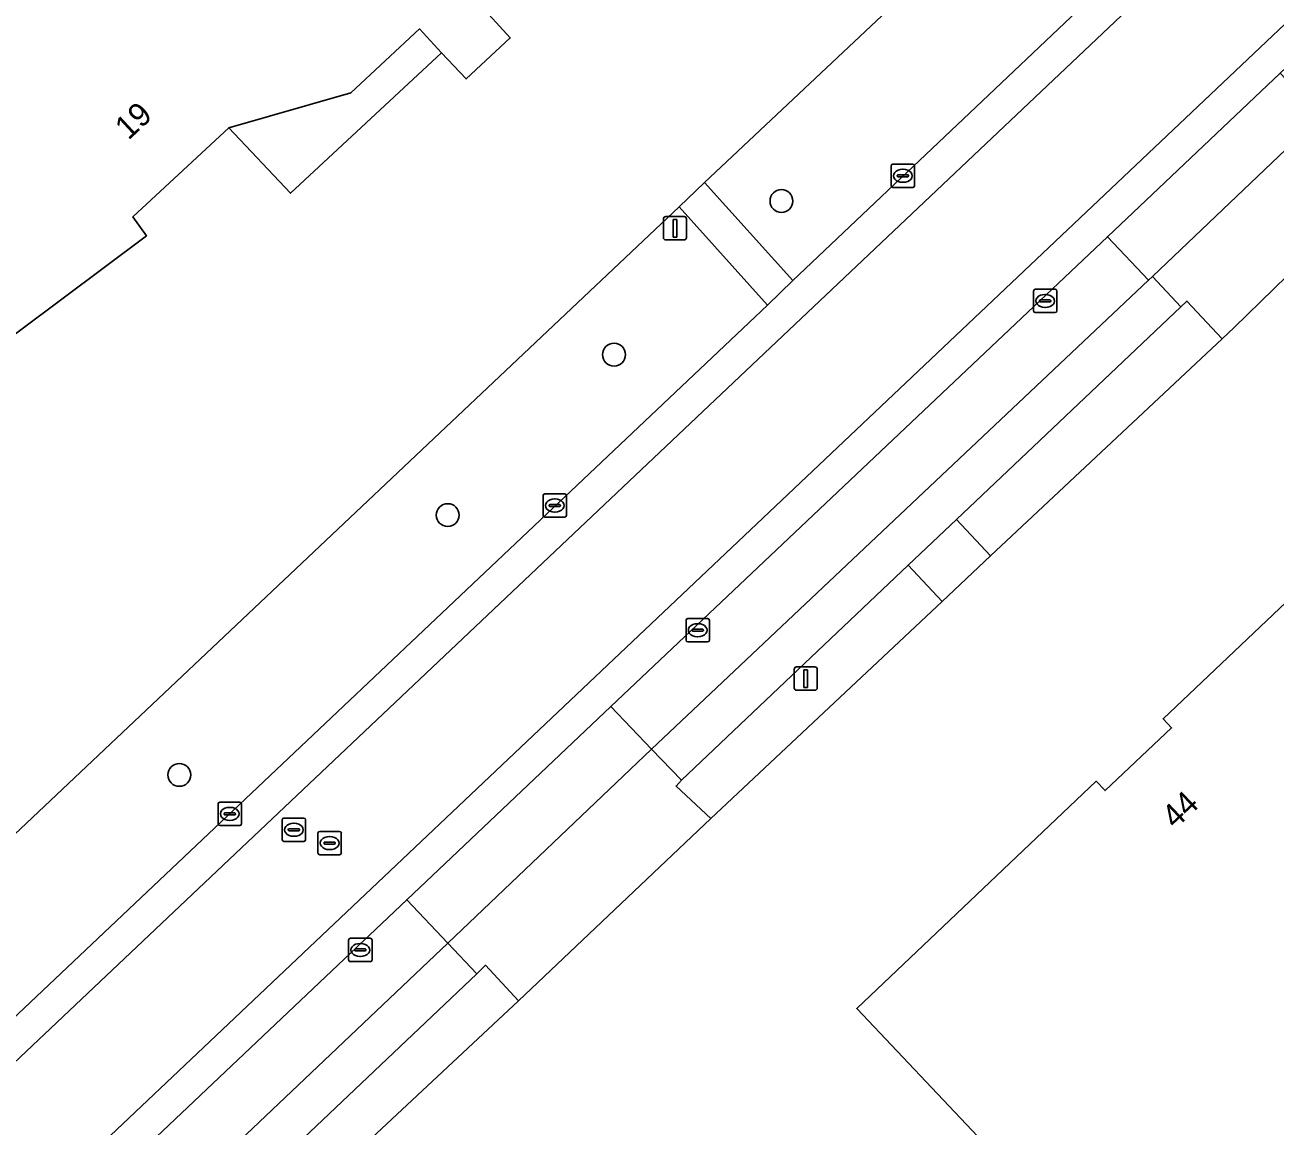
# Model space of a CAD drawing. Extents: x 156702 to 158052, y 387630 to 388992.
# Drawn here: x 157741 to 157794.6, y 388411.3 to 388458.5 of the extents above; entities that cross this region are included whole.
import ezdxf

# ---------------------------------------------------------------- set-up
doc = ezdxf.new("R2010")
doc.units = 0
for name, color, linetype in [('IMGEO_Berm_groen', 7, 'Continuous'), ('IMGEO_Boom', 7, 'Continuous'), ('IMGEO_Erf', 7, 'Continuous'), ('IMGEO_Groenvoorziening', 7, 'Continuous'), ('IMGEO_Kolk', 7, 'Continuous'), ('IMGEO_Lichtmast', 7, 'Continuous'), ('IMGEO_Pand', 7, 'Continuous'), ('IMGEO_Pand_nummerreeks', 7, 'Continuous'), ('IMGEO_Pand_overbouw', 7, 'Continuous'), ('IMGEO_Parkeervlak_open', 7, 'Continuous'), ('IMGEO_Rijbaan_lokaal_gesloten', 7, 'Continuous'), ('IMGEO_Rioolput', 7, 'Continuous'), ('IMGEO_Verkeersbordpaal', 7, 'Continuous'), ('IMGEO_Voetpad_open', 7, 'Continuous')]:
    doc.layers.add(name, color=color, linetype=linetype)

msp = doc.modelspace()

# ---------------------------------------------------------------- linework, layer by layer
at = {"layer": 'IMGEO_Berm_groen'}
msp.add_lwpolyline([(157799.053, 388483.441), (157798.811, 388483.771), (157794.961, 388480.951), (157795.152, 388480.693), (157796.754, 388477.777), (157795.516, 388475.573), (157788.977, 388469.333), (157788.87, 388469.419), (157770.108, 388451.766), (157773.891, 388447.573), (157795.288, 388467.846)], dxfattribs=at)
msp.add_lwpolyline([(157772.807, 388446.508), (157769.024, 388450.72), (157715.141, 388399.858), (157717.133, 388397.781), (157719.197, 388399.804), (157721.207, 388397.728)], close=True, dxfattribs=at)
at = {"layer": 'IMGEO_Boom'}
for centre in [(157773.406, 388450.975), (157766.234, 388444.394), (157759.109, 388437.518), (157747.611, 388426.388)]:
    msp.add_circle(centre, 0.489, dxfattribs=at)
at = {"layer": 'IMGEO_Erf'}
for points in [[(157780.944, 388485.335), (157784.71, 388481.246), (157762.612, 388460.811), (157761.599, 388461.832), (157759.801, 388460.159), (157761.786, 388457.966), (157759.898, 388456.205), (157758.849, 388457.329), (157757.899, 388458.347), (157754.963, 388455.611), (157749.735, 388454.115), (157745.623, 388450.301), (157746.202, 388449.487), (157707.991, 388420.9), (157704.997, 388424.904), (157689.835, 388445.184), (157694.111, 388448.366), (157686.05, 388459.123), (157681.815, 388464.773), (157694.419, 388474.218), (157682.965, 388489.503), (157670.362, 388480.058), (157658.428, 388495.983)], [(157828.567, 388476.717), (157827.02, 388475.574), (157819.744, 388469.314), (157819.109, 388469.983), (157810.78, 388462.732), (157797.894, 388450.521), (157792.808, 388445.559), (157792.292, 388445.075), (157782.368, 388435.768), (157780.291, 388433.819), (157770.375, 388424.519), (157762.137, 388416.71), (157750.411, 388405.749), (157741.215, 388396.791), (157739.918, 388395.57), (157734.391, 388390.366), (157712.553, 388369.817), (157711.355, 388368.682), (157705.627, 388363.261), (157681.507, 388340.173), (157681.329, 388340.003), (157675.827, 388334.804), (157653.403, 388313.608)], [(157627.449, 388318.044), (157654.429, 388341.395), (157664.141, 388350.795), (157692.355, 388378.104), (157701.62, 388386.983), (157703.834, 388389.244), (157706.743, 388391.918), (157715.141, 388399.858), (157769.024, 388450.72), (157770.108, 388451.766), (157788.87, 388469.419)]]:
    msp.add_lwpolyline(points, dxfattribs=at)
msp.add_lwpolyline([(157828.903, 388399.086), (157819.659, 388390.335), (157810.015, 388381.225), (157800.203, 388391.612), (157786.92, 388405.336), (157787, 388405.411), (157776.631, 388416.385), (157786.895, 388426.115), (157787.273, 388425.716), (157790.124, 388428.402), (157789.758, 388428.796), (157800.014, 388438.514), (157800.858, 388437.621), (157810.402, 388427.538), (157805.987, 388423.319), (157811.695, 388417.284)], close=True, dxfattribs=at)
at = {"layer": 'IMGEO_Groenvoorziening'}
for points in [[(157792.292, 388445.075), (157790.778, 388446.688), (157790.516, 388446.44), (157780.903, 388437.33), (157782.368, 388435.768)], [(157780.291, 388433.819), (157778.835, 388435.371), (157769.122, 388426.166), (157768.891, 388425.91), (157770.375, 388424.519)], [(157741.215, 388396.791), (157750.411, 388405.749), (157762.137, 388416.71), (157760.733, 388418.234), (157760.352, 388417.858), (157740.012, 388398.572), (157739.731, 388398.3)]]:
    msp.add_lwpolyline(points, close=True, dxfattribs=at)
at = {"layer": 'IMGEO_Kolk'}
for p, q in [((157778.184, 388452.557), (157779.036, 388452.557)), ((157778.109, 388451.631), (157778.109, 388452.483)), ((157778.368, 388452.051), (157778.368, 388452.063)), ((157778.806, 388452.014), (157778.408, 388452.014)), ((157778.411, 388452.1), (157778.809, 388452.1)), ((157778.597, 388452.337), (157778.622, 388452.337)), ((157778.852, 388452.063), (157778.852, 388452.051)), ((157779.11, 388452.483), (157779.11, 388451.631)), ((157779.036, 388451.557), (157778.184, 388451.557)), ((157778.62, 388451.777), (157778.595, 388451.777)), ((157784.282, 388447.193), (157785.134, 388447.193)), ((157784.207, 388446.267), (157784.207, 388447.119)), ((157784.466, 388446.687), (157784.466, 388446.699)), ((157784.904, 388446.65), (157784.506, 388446.65)), ((157784.509, 388446.736), (157784.907, 388446.736)), ((157784.695, 388446.973), (157784.72, 388446.973)), ((157784.95, 388446.699), (157784.95, 388446.687)), ((157785.208, 388447.119), (157785.208, 388446.267)), ((157785.134, 388446.193), (157784.282, 388446.193)), ((157784.718, 388446.413), (157784.693, 388446.413)), ((157763.196, 388437.504), (157763.196, 388438.356)), ((157763.271, 388438.43), (157764.123, 388438.43)), ((157763.684, 388438.21), (157763.709, 388438.21)), ((157764.197, 388438.356), (157764.197, 388437.504)), ((157763.455, 388437.924), (157763.455, 388437.936)), ((157763.893, 388437.887), (157763.495, 388437.887)), ((157763.498, 388437.973), (157763.896, 388437.973)), ((157763.707, 388437.65), (157763.682, 388437.65)), ((157763.939, 388437.936), (157763.939, 388437.924)), ((157764.123, 388437.43), (157763.271, 388437.43)), ((157769.318, 388432.16), (157769.318, 388433.012)), ((157769.393, 388433.086), (157770.245, 388433.086)), ((157769.806, 388432.866), (157769.831, 388432.866)), ((157770.319, 388433.012), (157770.319, 388432.16)), ((157769.577, 388432.58), (157769.577, 388432.592)), ((157770.015, 388432.543), (157769.617, 388432.543)), ((157769.62, 388432.629), (157770.018, 388432.629)), ((157769.829, 388432.306), (157769.804, 388432.306)), ((157770.061, 388432.592), (157770.061, 388432.58)), ((157770.245, 388432.086), (157769.393, 388432.086)), ((157749.344, 388425.217), (157750.196, 388425.217)), ((157749.269, 388424.291), (157749.269, 388425.143)), ((157749.528, 388424.711), (157749.528, 388424.723)), ((157749.966, 388424.674), (157749.568, 388424.674)), ((157749.571, 388424.76), (157749.969, 388424.76)), ((157749.757, 388424.997), (157749.782, 388424.997)), ((157750.012, 388424.723), (157750.012, 388424.711)), ((157750.27, 388425.143), (157750.27, 388424.291)), ((157750.196, 388424.217), (157749.344, 388424.217)), ((157749.78, 388424.437), (157749.755, 388424.437)), ((157754.864, 388418.46), (157754.864, 388419.312)), ((157754.939, 388419.386), (157755.791, 388419.386)), ((157755.865, 388419.312), (157755.865, 388418.46)), ((157755.123, 388418.88), (157755.123, 388418.892)), ((157755.561, 388418.843), (157755.163, 388418.843)), ((157755.166, 388418.929), (157755.564, 388418.929)), ((157755.352, 388419.166), (157755.377, 388419.166)), ((157755.607, 388418.892), (157755.607, 388418.88)), ((157755.791, 388418.386), (157754.939, 388418.386)), ((157755.375, 388418.606), (157755.35, 388418.606))]:
    msp.add_line(p, q, dxfattribs=at)
for points in [[(157778.184, 388452.557), (157779.036, 388452.557)], [(157778.109, 388451.631), (157778.109, 388452.483)], [(157779.11, 388452.483), (157779.11, 388451.631)], [(157779.036, 388451.557), (157778.184, 388451.557)], [(157784.282, 388447.193), (157785.134, 388447.193)], [(157784.207, 388446.267), (157784.207, 388447.119)], [(157785.208, 388447.119), (157785.208, 388446.267)], [(157785.134, 388446.193), (157784.282, 388446.193)], [(157763.196, 388437.504), (157763.196, 388438.356)], [(157763.271, 388438.43), (157764.123, 388438.43)], [(157764.197, 388438.356), (157764.197, 388437.504)], [(157764.123, 388437.43), (157763.271, 388437.43)], [(157769.318, 388432.16), (157769.318, 388433.012)], [(157769.393, 388433.086), (157770.245, 388433.086)], [(157770.319, 388433.012), (157770.319, 388432.16)], [(157770.245, 388432.086), (157769.393, 388432.086)], [(157749.344, 388425.217), (157750.196, 388425.217)], [(157749.269, 388424.291), (157749.269, 388425.143)], [(157750.27, 388425.143), (157750.27, 388424.291)], [(157750.196, 388424.217), (157749.344, 388424.217)], [(157754.864, 388418.46), (157754.864, 388419.312)], [(157754.939, 388419.386), (157755.791, 388419.386)], [(157755.865, 388419.312), (157755.865, 388418.46)], [(157755.791, 388418.386), (157754.939, 388418.386)]]:
    msp.add_lwpolyline(points, dxfattribs=at)
for centre, radius, start, end in [((157778.186, 388452.481), 0.0765, 91.552, 178.448), ((157778.186, 388452.481), 0.0765, 91.552, 178.448), ((157779.034, 388452.481), 0.0765, 1.552, 88.448), ((157779.034, 388452.481), 0.0765, 1.552, 88.448), ((157778.408, 388452.06), 0.0403, 85.8775, 175.7526), ((157778.405, 388452.05), 0.0366, 178.938, 274.7102), ((157778.809, 388452.057), 0.043, 264.8664, 352.4533), ((157778.813, 388452.062), 0.0386, 1.7309, 96.639), ((157778.186, 388451.633), 0.0765, 181.552, 268.448), ((157778.186, 388451.633), 0.0765, 181.552, 268.448), ((157779.034, 388451.633), 0.0765, 271.552, 358.448), ((157779.034, 388451.633), 0.0765, 271.552, 358.448), ((157784.284, 388447.117), 0.0765, 91.552, 178.448), ((157784.284, 388447.117), 0.0765, 91.552, 178.448), ((157785.132, 388447.117), 0.0765, 1.552, 88.448), ((157785.132, 388447.117), 0.0765, 1.552, 88.448), ((157784.506, 388446.696), 0.0403, 85.8775, 175.7526), ((157784.503, 388446.686), 0.0366, 178.938, 274.7102), ((157784.907, 388446.693), 0.043, 264.8664, 352.4533), ((157784.911, 388446.698), 0.0386, 1.7309, 96.639), ((157784.284, 388446.269), 0.0765, 181.552, 268.448), ((157784.284, 388446.269), 0.0765, 181.552, 268.448), ((157785.132, 388446.269), 0.0765, 271.552, 358.448), ((157785.132, 388446.269), 0.0765, 271.552, 358.448), ((157763.273, 388438.354), 0.0765, 91.552, 178.448), ((157763.273, 388438.354), 0.0765, 91.552, 178.448), ((157764.121, 388438.354), 0.0765, 1.552, 88.448), ((157764.121, 388438.354), 0.0765, 1.552, 88.448), ((157763.273, 388437.506), 0.0765, 181.552, 268.448), ((157763.273, 388437.506), 0.0765, 181.552, 268.448), ((157763.495, 388437.933), 0.0403, 85.8775, 175.7526), ((157763.492, 388437.923), 0.0366, 178.938, 274.7102), ((157763.896, 388437.93), 0.043, 264.8664, 352.4533), ((157763.9, 388437.935), 0.0386, 1.7309, 96.639), ((157764.121, 388437.506), 0.0765, 271.552, 358.448), ((157764.121, 388437.506), 0.0765, 271.552, 358.448), ((157769.395, 388433.01), 0.0765, 91.552, 178.448), ((157769.395, 388433.01), 0.0765, 91.552, 178.448), ((157770.243, 388433.01), 0.0765, 1.552, 88.448), ((157770.243, 388433.01), 0.0765, 1.552, 88.448), ((157769.395, 388432.162), 0.0765, 181.552, 268.448), ((157769.395, 388432.162), 0.0765, 181.552, 268.448), ((157769.617, 388432.589), 0.0403, 85.8775, 175.7526), ((157769.614, 388432.579), 0.0366, 178.938, 274.7102), ((157770.018, 388432.586), 0.043, 264.8664, 352.4533), ((157770.022, 388432.591), 0.0386, 1.7309, 96.639), ((157770.243, 388432.162), 0.0765, 271.552, 358.448), ((157770.243, 388432.162), 0.0765, 271.552, 358.448), ((157749.346, 388425.141), 0.0765, 91.552, 178.448), ((157749.346, 388425.141), 0.0765, 91.552, 178.448), ((157750.194, 388425.141), 0.0765, 1.552, 88.448), ((157750.194, 388425.141), 0.0765, 1.552, 88.448), ((157749.568, 388424.72), 0.0403, 85.8775, 175.7526), ((157749.565, 388424.71), 0.0366, 178.938, 274.7102), ((157749.969, 388424.717), 0.043, 264.8664, 352.4533), ((157749.973, 388424.722), 0.0386, 1.7309, 96.639), ((157749.346, 388424.293), 0.0765, 181.552, 268.448), ((157749.346, 388424.293), 0.0765, 181.552, 268.448), ((157750.194, 388424.293), 0.0765, 271.552, 358.448), ((157750.194, 388424.293), 0.0765, 271.552, 358.448), ((157754.941, 388419.31), 0.0765, 91.552, 178.448), ((157754.941, 388419.31), 0.0765, 91.552, 178.448), ((157755.789, 388419.31), 0.0765, 1.552, 88.448), ((157755.789, 388419.31), 0.0765, 1.552, 88.448), ((157755.163, 388418.889), 0.0403, 85.8775, 175.7526), ((157755.16, 388418.879), 0.0366, 178.938, 274.7102), ((157755.564, 388418.886), 0.043, 264.8664, 352.4533), ((157755.568, 388418.891), 0.0386, 1.7309, 96.639), ((157754.941, 388418.462), 0.0765, 181.552, 268.448), ((157754.941, 388418.462), 0.0765, 181.552, 268.448), ((157755.789, 388418.462), 0.0765, 271.552, 358.448), ((157755.789, 388418.462), 0.0765, 271.552, 358.448)]:
    msp.add_arc(centre, radius, start, end, dxfattribs=at)
for centre, major_axis, ratio, start_param, end_param in [((157778.596, 388452.057), (-0.387, 0.002), 0.722429, 4.712389, 7.853982), ((157778.621, 388452.057), (-0.39, 0.002), 0.717154, 1.570796, 4.712389), ((157784.694, 388446.693), (-0.387, 0.002), 0.722429, 4.712389, 7.853982), ((157784.719, 388446.693), (-0.39, 0.002), 0.717154, 1.570796, 4.712389), ((157763.683, 388437.93), (-0.387, 0.002), 0.722429, 4.712389, 7.853982), ((157763.708, 388437.93), (-0.39, 0.002), 0.717154, 1.570796, 4.712389), ((157769.805, 388432.586), (-0.387, 0.002), 0.722429, 4.712389, 7.853982), ((157769.83, 388432.586), (-0.39, 0.002), 0.717154, 1.570796, 4.712389), ((157749.756, 388424.717), (-0.387, 0.002), 0.722429, 4.712389, 7.853982), ((157749.781, 388424.717), (-0.39, 0.002), 0.717154, 1.570796, 4.712389), ((157755.351, 388418.886), (-0.387, 0.002), 0.722429, 4.712389, 7.853982), ((157755.376, 388418.886), (-0.39, 0.002), 0.717154, 1.570796, 4.712389)]:
    msp.add_ellipse(centre, major_axis=major_axis, ratio=ratio, start_param=start_param, end_param=end_param, dxfattribs=at)
at = {"layer": 'IMGEO_Lichtmast'}
for p, q in [((157773.952, 388430.112), (157773.952, 388430.912)), ((157773.952, 388430.912), (157773.952, 388430.112)), ((157774.052, 388431.012), (157774.842, 388431.012)), ((157774.842, 388431.012), (157774.052, 388431.012)), ((157774.942, 388430.912), (157774.942, 388430.112)), ((157774.942, 388430.112), (157774.942, 388430.912)), ((157774.842, 388430.012), (157774.052, 388430.012)), ((157774.052, 388430.012), (157774.842, 388430.012))]:
    msp.add_line(p, q, dxfattribs=at)
msp.add_lwpolyline([(157774.372, 388430.887), (157774.522, 388430.887), (157774.522, 388430.137), (157774.372, 388430.137), (157774.372, 388430.887)], dxfattribs=at)
for centre, start, end in [((157774.052, 388430.912), 90, 180), ((157774.052, 388430.912), 90, 180), ((157774.842, 388430.912), 0, 90), ((157774.842, 388430.912), 360, 90), ((157774.052, 388430.112), 180, 270), ((157774.052, 388430.112), 180, 270), ((157774.842, 388430.112), 270, 0), ((157774.842, 388430.112), 270, 0)]:
    msp.add_arc(centre, 0.1, start, end, dxfattribs=at)
at = {"layer": 'IMGEO_Pand'}
msp.add_lwpolyline([(157658.428, 388495.983), (157670.362, 388480.058), (157682.965, 388489.503), (157694.419, 388474.218), (157681.815, 388464.773), (157686.05, 388459.123), (157694.111, 388448.366), (157689.835, 388445.184), (157704.997, 388424.904), (157707.991, 388420.9), (157746.202, 388449.487), (157745.623, 388450.301), (157749.735, 388454.115), (157754.963, 388455.611), (157757.899, 388458.347), (157758.849, 388457.329), (157759.898, 388456.205), (157761.786, 388457.966), (157759.801, 388460.159), (157761.599, 388461.832), (157762.612, 388460.811), (157784.71, 388481.246), (157780.944, 388485.335)], dxfattribs=at)
msp.add_lwpolyline([(157800.858, 388437.621), (157800.014, 388438.514), (157789.758, 388428.796), (157790.124, 388428.402), (157787.273, 388425.716), (157786.895, 388426.115), (157776.631, 388416.385), (157787, 388405.411), (157786.92, 388405.336), (157800.203, 388391.612), (157810.015, 388381.225), (157819.659, 388390.335), (157828.903, 388399.086), (157811.695, 388417.284), (157805.987, 388423.319), (157810.402, 388427.538)], close=True, dxfattribs=at)
at = {"layer": 'IMGEO_Pand_overbouw'}
msp.add_lwpolyline([(157758.849, 388457.329), (157757.899, 388458.347), (157754.963, 388455.611), (157749.735, 388454.115), (157752.367, 388451.307)], close=True, dxfattribs=at)
at = {"layer": 'IMGEO_Parkeervlak_open'}
for points in [[(157789.133, 388447.581), (157787.371, 388449.448), (157766.1, 388429.315), (157767.832, 388427.485)], [(157759.112, 388419.181), (157757.354, 388421.039), (157736.97, 388401.746), (157738.748, 388399.867)]]:
    msp.add_lwpolyline(points, close=True, dxfattribs=at)
at = {"layer": 'IMGEO_Rijbaan_lokaal_gesloten'}
for points in [[(157925.989, 388541.781), (157925.789, 388544.405), (157924.816, 388544.354), (157921.978, 388543.651), (157920.425, 388542.954), (157916.373, 388540.433), (157884.271, 388521.013), (157881.592, 388519.374), (157838.65, 388493.098), (157832.229, 388488.942), (157827.136, 388485.429), (157822.012, 388481.702), (157814.126, 388475.59), (157808.05, 388470.514), (157801.977, 388465.115), (157800.565, 388463.859), (157728.664, 388395.811), (157729.626, 388394.795), (157736.97, 388401.746), (157757.354, 388421.039), (157766.1, 388429.315), (157787.371, 388449.448), (157794.773, 388456.453), (157801.348, 388462.676)], [(157722.575, 388397.084), (157798.497, 388468.895), (157797.546, 388469.921), (157795.288, 388467.846), (157773.891, 388447.573), (157772.807, 388446.508), (157721.207, 388397.728), (157693.937, 388371.932), (157669.377, 388348.694), (157655.751, 388335.812), (157635.35, 388316.566)], [(157640.155, 388312.044), (157727.538, 388394.745), (157728.664, 388395.811), (157800.565, 388463.859), (157801.977, 388465.115), (157798.497, 388468.895), (157722.575, 388397.084), (157652.853, 388331.137), (157631.518, 388311.458)]]:
    msp.add_lwpolyline(points, dxfattribs=at)
at = {"layer": 'IMGEO_Rioolput'}
for p, q in [((157752.017, 388423.611), (157752.017, 388424.463)), ((157752.092, 388424.537), (157752.944, 388424.537)), ((157752.505, 388424.317), (157752.53, 388424.317)), ((157753.018, 388424.463), (157753.018, 388423.611)), ((157752.276, 388424.031), (157752.276, 388424.043)), ((157752.714, 388423.994), (157752.316, 388423.994)), ((157752.319, 388424.08), (157752.717, 388424.08)), ((157752.528, 388423.757), (157752.503, 388423.757)), ((157752.76, 388424.043), (157752.76, 388424.031)), ((157753.549, 388423.042), (157753.549, 388423.894)), ((157753.624, 388423.968), (157754.476, 388423.968)), ((157754.037, 388423.748), (157754.062, 388423.748)), ((157754.55, 388423.894), (157754.55, 388423.042)), ((157752.944, 388423.537), (157752.092, 388423.537)), ((157753.808, 388423.462), (157753.808, 388423.474)), ((157754.246, 388423.425), (157753.848, 388423.425)), ((157753.851, 388423.511), (157754.249, 388423.511)), ((157754.06, 388423.188), (157754.035, 388423.188)), ((157754.292, 388423.474), (157754.292, 388423.462)), ((157754.476, 388422.968), (157753.624, 388422.968))]:
    msp.add_line(p, q, dxfattribs=at)
for points in [[(157752.017, 388423.611), (157752.017, 388424.463)], [(157752.092, 388424.537), (157752.944, 388424.537)], [(157753.018, 388424.463), (157753.018, 388423.611)], [(157753.549, 388423.042), (157753.549, 388423.894)], [(157753.624, 388423.968), (157754.476, 388423.968)], [(157754.55, 388423.894), (157754.55, 388423.042)], [(157752.944, 388423.537), (157752.092, 388423.537)], [(157754.476, 388422.968), (157753.624, 388422.968)]]:
    msp.add_lwpolyline(points, dxfattribs=at)
for centre, radius, start, end in [((157752.094, 388424.461), 0.0765, 91.552, 178.448), ((157752.094, 388424.461), 0.0765, 91.552, 178.448), ((157752.942, 388424.461), 0.0765, 1.552, 88.448), ((157752.942, 388424.461), 0.0765, 1.552, 88.448), ((157752.094, 388423.613), 0.0765, 181.552, 268.448), ((157752.094, 388423.613), 0.0765, 181.552, 268.448), ((157752.316, 388424.04), 0.0403, 85.8775, 175.7526), ((157752.313, 388424.03), 0.0366, 178.938, 274.7102), ((157752.717, 388424.037), 0.043, 264.8664, 352.4533), ((157752.721, 388424.042), 0.0386, 1.7309, 96.639), ((157752.942, 388423.613), 0.0765, 271.552, 358.448), ((157752.942, 388423.613), 0.0765, 271.552, 358.448), ((157753.626, 388423.892), 0.0765, 91.552, 178.448), ((157753.626, 388423.892), 0.0765, 91.552, 178.448), ((157754.474, 388423.892), 0.0765, 1.552, 88.448), ((157754.474, 388423.892), 0.0765, 1.552, 88.448), ((157753.626, 388423.044), 0.0765, 181.552, 268.448), ((157753.626, 388423.044), 0.0765, 181.552, 268.448), ((157753.848, 388423.471), 0.0403, 85.8775, 175.7526), ((157753.845, 388423.461), 0.0366, 178.938, 274.7102), ((157754.249, 388423.468), 0.043, 264.8664, 352.4533), ((157754.253, 388423.473), 0.0386, 1.7309, 96.639), ((157754.474, 388423.044), 0.0765, 271.552, 358.448), ((157754.474, 388423.044), 0.0765, 271.552, 358.448)]:
    msp.add_arc(centre, radius, start, end, dxfattribs=at)
for centre, major_axis, ratio, start_param, end_param in [((157752.504, 388424.037), (-0.387, 0.002), 0.722429, 4.712389, 7.853982), ((157752.529, 388424.037), (-0.39, 0.002), 0.717154, 1.570796, 4.712389), ((157754.036, 388423.468), (-0.387, 0.002), 0.722429, 4.712389, 7.853982), ((157754.061, 388423.468), (-0.39, 0.002), 0.717154, 1.570796, 4.712389)]:
    msp.add_ellipse(centre, major_axis=major_axis, ratio=ratio, start_param=start_param, end_param=end_param, dxfattribs=at)
at = {"layer": 'IMGEO_Verkeersbordpaal'}
for p, q in [((157768.349, 388449.407), (157768.349, 388450.207)), ((157768.349, 388450.207), (157768.349, 388449.407)), ((157768.449, 388450.307), (157769.239, 388450.307)), ((157769.239, 388450.307), (157768.449, 388450.307)), ((157769.339, 388450.207), (157769.339, 388449.407)), ((157769.339, 388449.407), (157769.339, 388450.207)), ((157769.239, 388449.307), (157768.449, 388449.307)), ((157768.449, 388449.307), (157769.239, 388449.307))]:
    msp.add_line(p, q, dxfattribs=at)
msp.add_lwpolyline([(157768.769, 388450.182), (157768.919, 388450.182), (157768.919, 388449.432), (157768.769, 388449.432), (157768.769, 388450.182)], dxfattribs=at)
for centre, start, end in [((157768.449, 388450.207), 90, 180), ((157768.449, 388450.207), 90, 180), ((157769.239, 388450.207), 0, 90), ((157769.239, 388450.207), 360, 90), ((157768.449, 388449.407), 180, 270), ((157768.449, 388449.407), 180, 270), ((157769.239, 388449.407), 270, 0), ((157769.239, 388449.407), 270, 0)]:
    msp.add_arc(centre, 0.1, start, end, dxfattribs=at)
at = {"layer": 'IMGEO_Voetpad_open'}
for points in [[(157796.519, 388454.609), (157794.773, 388456.453), (157787.371, 388449.448), (157789.133, 388447.581), (157789.298, 388447.736)], [(157797.894, 388450.521), (157796.45, 388452.142), (157797.708, 388453.347), (157797.273, 388453.809), (157796.519, 388454.609), (157789.298, 388447.736), (157790.516, 388446.44), (157790.778, 388446.688), (157792.292, 388445.075), (157792.808, 388445.559)], [(157773.891, 388447.573), (157770.108, 388451.766), (157769.024, 388450.72), (157772.807, 388446.508)], [(157780.903, 388437.33), (157790.516, 388446.44), (157789.298, 388447.736), (157789.133, 388447.581), (157767.832, 388427.485), (157769.122, 388426.166), (157778.835, 388435.371)], [(157782.368, 388435.768), (157780.903, 388437.33), (157778.835, 388435.371), (157780.291, 388433.819)], [(157767.832, 388427.485), (157766.1, 388429.315), (157757.354, 388421.039), (157759.112, 388419.181)], [(157759.112, 388419.181), (157760.352, 388417.858), (157760.733, 388418.234), (157762.137, 388416.71), (157770.375, 388424.519), (157768.891, 388425.91), (157769.122, 388426.166), (157767.832, 388427.485)], [(157740.012, 388398.572), (157760.352, 388417.858), (157759.112, 388419.181), (157738.748, 388399.867)]]:
    msp.add_lwpolyline(points, close=True, dxfattribs=at)

# ---------------------------------------------------------------- texts
at = {"layer": 'IMGEO_Pand_nummerreeks'}
for s, rotation, p in [('19', 42.8458, (157745.427, 388453.556)), ('44', 43.2922, (157790.277, 388424.04))]:
    msp.add_text(s, height=1, rotation=rotation, dxfattribs=at).set_placement(p)

doc.saveas('drawing.dxf')
